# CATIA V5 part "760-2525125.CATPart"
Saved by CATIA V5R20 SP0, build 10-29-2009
Part number: 760-2525125
Source: Unknown
Property "A": "25.000"
Property "ARTICLENO": "760-2525125"
Property "BOMINFO": "760-2525125"
Property "CODE": "760-2525125"
Property "K": "62.500"
Property "L": "125.000"
Property "LINA": "760-2525125"
Property "NB": "760-2525125"
Property "NBSYN": "$CODE."
Property "NN": "760"
Property "NT": "Key"
Property "SUPPLIER": "CF"
Bounding box of the stored display mesh (mm): x -62.5 to 62.5, y 0 to 25, z -12.5 to 12.5
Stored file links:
  C:\Users\Utente\Desktop\3D files 760\760-2525125.CATPart
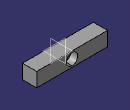
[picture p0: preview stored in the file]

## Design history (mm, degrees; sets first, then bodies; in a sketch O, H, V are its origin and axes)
Body1 "Geometry.1" (main body)
  Solid1 "760-2525125.catpart": solid without history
